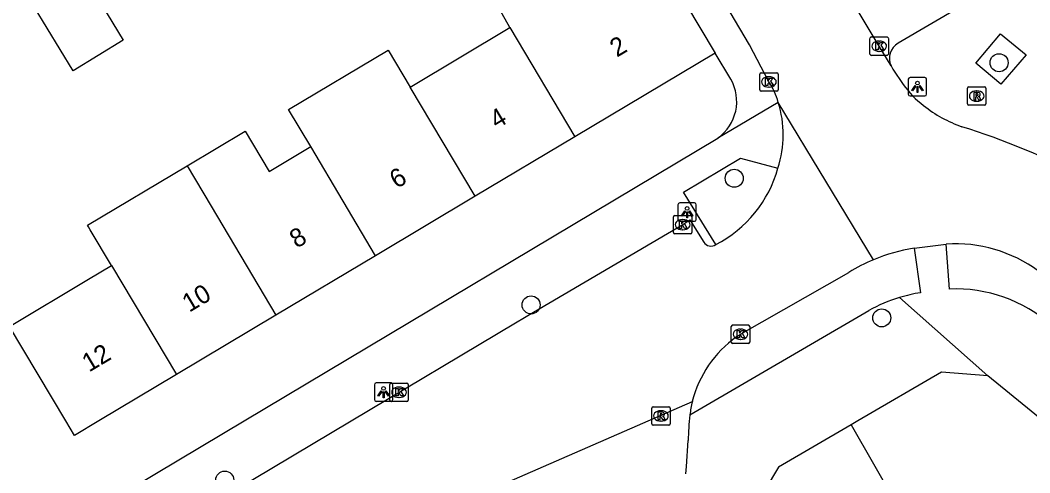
# Model space of a CAD drawing. Extents: x 159222 to 160346, y 381249 to 382166.
# Drawn here: x 160195.3 to 160250.2, y 381997.2 to 382021.7 of the extents above; entities that cross this region are included whole.
import ezdxf

# ---------------------------------------------------------------- set-up
doc = ezdxf.new("R2010")
doc.units = 0
for name, color, linetype in [('IMGEO_Boom', 7, 'Continuous'), ('IMGEO_Kolk', 7, 'Continuous'), ('IMGEO_Lichtpunt', 7, 'Continuous'), ('IMGEO_Pand', 7, 'Continuous'), ('IMGEO_Pand_nummerreeks', 7, 'Continuous'), ('IMGEO_Rijbaan_lokaal_open', 7, 'Continuous'), ('IMGEO_Rioolput', 7, 'Continuous'), ('IMGEO_Voetpad_open', 7, 'Continuous')]:
    doc.layers.add(name, color=color, linetype=linetype)

msp = doc.modelspace()

# ---------------------------------------------------------------- linework, layer by layer
at = {"layer": 'IMGEO_Boom'}
for centre in [(160248.507, 382019.429), (160234.114, 382013.158), (160223.079, 382006.288), (160242.131, 382005.588), (160206.437, 381996.785)]:
    msp.add_circle(centre, 0.489, dxfattribs=at)
at = {"layer": 'IMGEO_Kolk'}
for p, q in [((160241.566, 382020.825), (160242.418, 382020.825)), ((160241.491, 382019.899), (160241.491, 382020.751)), ((160241.979, 382020.605), (160242.004, 382020.605)), ((160242.492, 382020.751), (160242.492, 382019.899)), ((160242.418, 382019.825), (160241.566, 382019.825)), ((160242.002, 382020.045), (160241.977, 382020.045)), ((160235.499, 382017.96), (160235.499, 382018.812)), ((160235.574, 382018.886), (160236.426, 382018.886)), ((160235.987, 382018.666), (160236.012, 382018.666)), ((160236.5, 382018.812), (160236.5, 382017.96)), ((160236.01, 382018.106), (160235.985, 382018.106)), ((160236.426, 382017.886), (160235.574, 382017.886)), ((160230.815, 382010.217), (160230.815, 382011.069)), ((160230.89, 382011.143), (160231.742, 382011.143)), ((160231.303, 382010.923), (160231.328, 382010.923)), ((160231.816, 382011.069), (160231.816, 382010.217)), ((160231.742, 382010.143), (160230.89, 382010.143)), ((160231.326, 382010.363), (160231.301, 382010.363)), ((160233.956, 382004.274), (160233.956, 382005.126)), ((160234.031, 382005.2), (160234.883, 382005.2)), ((160234.444, 382004.98), (160234.469, 382004.98)), ((160234.957, 382005.126), (160234.957, 382004.274)), ((160234.467, 382004.42), (160234.442, 382004.42)), ((160234.883, 382004.2), (160234.031, 382004.2)), ((160215.407, 382001.125), (160215.407, 382001.977)), ((160215.482, 382002.051), (160216.334, 382002.051)), ((160215.895, 382001.831), (160215.92, 382001.831)), ((160216.408, 382001.977), (160216.408, 382001.125)), ((160216.334, 382001.051), (160215.482, 382001.051)), ((160215.918, 382001.271), (160215.893, 382001.271))]:
    msp.add_line(p, q, dxfattribs=at)
for points in [[(160241.566, 382020.825), (160242.418, 382020.825)], [(160241.491, 382019.899), (160241.491, 382020.751)], [(160241.812, 382020.525), (160241.935, 382020.525), (160241.935, 382020.374), (160242.065, 382020.525), (160242.229, 382020.525), (160242.083, 382020.374), (160242.236, 382020.125), (160242.084, 382020.125), (160241.999, 382020.289), (160241.935, 382020.222), (160241.935, 382020.125), (160241.812, 382020.125), (160241.812, 382020.525)], [(160242.492, 382020.751), (160242.492, 382019.899)], [(160242.418, 382019.825), (160241.566, 382019.825)], [(160235.499, 382017.96), (160235.499, 382018.812)], [(160235.574, 382018.886), (160236.426, 382018.886)], [(160236.5, 382018.812), (160236.5, 382017.96)], [(160235.82, 382018.586), (160235.943, 382018.586), (160235.943, 382018.435), (160236.073, 382018.586), (160236.237, 382018.586), (160236.091, 382018.435), (160236.244, 382018.186), (160236.092, 382018.186), (160236.007, 382018.35), (160235.943, 382018.283), (160235.943, 382018.186), (160235.82, 382018.186), (160235.82, 382018.586)], [(160236.426, 382017.886), (160235.574, 382017.886)], [(160230.815, 382010.217), (160230.815, 382011.069)], [(160230.89, 382011.143), (160231.742, 382011.143)], [(160231.816, 382011.069), (160231.816, 382010.217)], [(160231.136, 382010.843), (160231.259, 382010.843), (160231.259, 382010.692), (160231.389, 382010.843), (160231.553, 382010.843), (160231.407, 382010.692), (160231.56, 382010.443), (160231.408, 382010.443), (160231.323, 382010.607), (160231.259, 382010.54), (160231.259, 382010.443), (160231.136, 382010.443), (160231.136, 382010.843)], [(160231.742, 382010.143), (160230.89, 382010.143)], [(160233.956, 382004.274), (160233.956, 382005.126)], [(160234.031, 382005.2), (160234.883, 382005.2)], [(160234.277, 382004.9), (160234.4, 382004.9), (160234.4, 382004.749), (160234.53, 382004.9), (160234.694, 382004.9), (160234.548, 382004.749), (160234.701, 382004.5), (160234.549, 382004.5), (160234.464, 382004.664), (160234.4, 382004.597), (160234.4, 382004.5), (160234.277, 382004.5), (160234.277, 382004.9)], [(160234.957, 382005.126), (160234.957, 382004.274)], [(160234.883, 382004.2), (160234.031, 382004.2)], [(160215.407, 382001.125), (160215.407, 382001.977)], [(160215.482, 382002.051), (160216.334, 382002.051)], [(160215.728, 382001.751), (160215.851, 382001.751), (160215.851, 382001.6), (160215.981, 382001.751), (160216.145, 382001.751), (160215.999, 382001.6), (160216.152, 382001.351), (160216, 382001.351), (160215.915, 382001.515), (160215.851, 382001.448), (160215.851, 382001.351), (160215.728, 382001.351), (160215.728, 382001.751)], [(160216.408, 382001.977), (160216.408, 382001.125)], [(160216.334, 382001.051), (160215.482, 382001.051)]]:
    msp.add_lwpolyline(points, dxfattribs=at)
for centre, start, end in [((160241.568, 382020.749), 91.552, 178.448), ((160241.568, 382020.749), 91.552, 178.448), ((160242.416, 382020.749), 1.552, 88.448), ((160242.416, 382020.749), 1.552, 88.448), ((160241.568, 382019.901), 181.552, 268.448), ((160241.568, 382019.901), 181.552, 268.448), ((160242.416, 382019.901), 271.552, 358.448), ((160242.416, 382019.901), 271.552, 358.448), ((160235.576, 382018.81), 91.552, 178.448), ((160235.576, 382018.81), 91.552, 178.448), ((160236.424, 382018.81), 1.552, 88.448), ((160236.424, 382018.81), 1.552, 88.448), ((160235.576, 382017.962), 181.552, 268.448), ((160235.576, 382017.962), 181.552, 268.448), ((160236.424, 382017.962), 271.552, 358.448), ((160236.424, 382017.962), 271.552, 358.448), ((160230.892, 382011.067), 91.552, 178.448), ((160230.892, 382011.067), 91.552, 178.448), ((160231.74, 382011.067), 1.552, 88.448), ((160231.74, 382011.067), 1.552, 88.448), ((160230.892, 382010.219), 181.552, 268.448), ((160230.892, 382010.219), 181.552, 268.448), ((160231.74, 382010.219), 271.552, 358.448), ((160231.74, 382010.219), 271.552, 358.448), ((160234.033, 382005.124), 91.552, 178.448), ((160234.033, 382005.124), 91.552, 178.448), ((160234.881, 382005.124), 1.552, 88.448), ((160234.881, 382005.124), 1.552, 88.448), ((160234.033, 382004.276), 181.552, 268.448), ((160234.033, 382004.276), 181.552, 268.448), ((160234.881, 382004.276), 271.552, 358.448), ((160234.881, 382004.276), 271.552, 358.448), ((160215.484, 382001.975), 91.552, 178.448), ((160215.484, 382001.975), 91.552, 178.448), ((160216.332, 382001.975), 1.552, 88.448), ((160216.332, 382001.975), 1.552, 88.448), ((160215.484, 382001.127), 181.552, 268.448), ((160215.484, 382001.127), 181.552, 268.448), ((160216.332, 382001.127), 271.552, 358.448), ((160216.332, 382001.127), 271.552, 358.448)]:
    msp.add_arc(centre, 0.0765, start, end, dxfattribs=at)
for centre, major_axis, ratio, start_param, end_param in [((160241.978, 382020.325), (-0.387, 0.002), 0.722429, 4.712389, 7.853982), ((160242.003, 382020.325), (-0.39, 0.002), 0.717154, 1.570796, 4.712389), ((160235.986, 382018.386), (-0.387, 0.002), 0.722429, 4.712389, 7.853982), ((160236.011, 382018.386), (-0.39, 0.002), 0.717154, 1.570796, 4.712389), ((160231.302, 382010.643), (-0.387, 0.002), 0.722429, 4.712389, 7.853982), ((160231.327, 382010.643), (-0.39, 0.002), 0.717154, 1.570796, 4.712389), ((160234.443, 382004.7), (-0.387, 0.002), 0.722429, 4.712389, 7.853982), ((160234.468, 382004.7), (-0.39, 0.002), 0.717154, 1.570796, 4.712389), ((160215.894, 382001.551), (-0.387, 0.002), 0.722429, 4.712389, 7.853982), ((160215.919, 382001.551), (-0.39, 0.002), 0.717154, 1.570796, 4.712389)]:
    msp.add_ellipse(centre, major_axis=major_axis, ratio=ratio, start_param=start_param, end_param=end_param, dxfattribs=at)
at = {"layer": 'IMGEO_Lichtpunt'}
for p, q in [((160244.474, 382018.622), (160243.666, 382018.622)), ((160244.474, 382018.622), (160243.666, 382018.622)), ((160243.572, 382018.527), (160243.572, 382017.72)), ((160243.572, 382018.527), (160243.572, 382017.72)), ((160244.568, 382017.72), (160244.568, 382018.527)), ((160244.568, 382017.72), (160244.568, 382018.527)), ((160243.666, 382017.626), (160244.474, 382017.626)), ((160243.666, 382017.626), (160244.474, 382017.626)), ((160231.06, 382011.727), (160231.06, 382010.92)), ((160231.06, 382011.727), (160231.06, 382010.92)), ((160231.962, 382011.822), (160231.154, 382011.822)), ((160231.962, 382011.822), (160231.154, 382011.822)), ((160232.056, 382010.92), (160232.056, 382011.727)), ((160232.056, 382010.92), (160232.056, 382011.727)), ((160231.154, 382010.826), (160231.962, 382010.826)), ((160231.154, 382010.826), (160231.962, 382010.826)), ((160214.57, 382001.96), (160214.57, 382001.153)), ((160214.57, 382001.96), (160214.57, 382001.153)), ((160215.472, 382002.055), (160214.664, 382002.055)), ((160215.472, 382002.055), (160214.664, 382002.055)), ((160215.566, 382001.153), (160215.566, 382001.96)), ((160215.566, 382001.153), (160215.566, 382001.96)), ((160214.664, 382001.059), (160215.472, 382001.059)), ((160214.664, 382001.059), (160215.472, 382001.059))]:
    msp.add_line(p, q, dxfattribs=at)
for points in [[(160243.946, 382018.191), (160243.985, 382018.163), (160243.797, 382017.901), (160243.759, 382017.928), (160243.946, 382018.191)], [(160244.048, 382018.143), (160244.095, 382018.143), (160244.095, 382017.821), (160244.048, 382017.821), (160244.048, 382018.143)], [(160244.158, 382018.163), (160244.196, 382018.19), (160244.383, 382017.928), (160244.344, 382017.9), (160244.158, 382018.163)], [(160231.434, 382011.391), (160231.473, 382011.363), (160231.285, 382011.101), (160231.247, 382011.128), (160231.434, 382011.391)], [(160231.536, 382011.343), (160231.583, 382011.343), (160231.583, 382011.021), (160231.536, 382011.021), (160231.536, 382011.343)], [(160231.646, 382011.363), (160231.684, 382011.39), (160231.871, 382011.128), (160231.832, 382011.1), (160231.646, 382011.363)], [(160214.944, 382001.624), (160214.983, 382001.596), (160214.795, 382001.334), (160214.757, 382001.361), (160214.944, 382001.624)], [(160215.156, 382001.596), (160215.194, 382001.623), (160215.381, 382001.361), (160215.342, 382001.333), (160215.156, 382001.596)], [(160215.046, 382001.576), (160215.093, 382001.576), (160215.093, 382001.254), (160215.046, 382001.254), (160215.046, 382001.576)]]:
    msp.add_lwpolyline(points, dxfattribs=at)
for centre in [(160244.071, 382018.325), (160231.559, 382011.525), (160215.069, 382001.758)]:
    msp.add_circle(centre, 0.0994, dxfattribs=at)
for centre, start, end in [((160243.666, 382018.527), 90, 180), ((160243.666, 382018.527), 90, 180), ((160244.474, 382018.527), 0, 90), ((160244.474, 382018.527), 0, 90), ((160243.666, 382017.72), 180, 270), ((160243.666, 382017.72), 180, 270), ((160244.474, 382017.72), 270, 0), ((160244.474, 382017.72), 270, 360), ((160231.154, 382011.727), 90, 180), ((160231.154, 382011.727), 90, 180), ((160231.962, 382011.727), 0, 90), ((160231.962, 382011.727), 0, 90), ((160231.154, 382010.92), 180, 270), ((160231.154, 382010.92), 180, 270), ((160231.962, 382010.92), 270, 0), ((160231.962, 382010.92), 270, 360), ((160214.664, 382001.96), 90, 180), ((160214.664, 382001.96), 90, 180), ((160215.472, 382001.96), 0, 90), ((160215.472, 382001.96), 0, 90), ((160214.664, 382001.153), 180, 270), ((160214.664, 382001.153), 180, 270), ((160215.472, 382001.153), 270, 0), ((160215.472, 382001.153), 270, 360)]:
    msp.add_arc(centre, 0.0946, start, end, dxfattribs=at)
at = {"layer": 'IMGEO_Pand'}
for points in [[(160221.931, 382021.33), (160220.691, 382023.549), (160223.954, 382025.494), (160228.248, 382028.054)], [(160228.248, 382028.054), (160233.082, 382019.946)], [(160196.087, 382022.455), (160198.814, 382024.117), (160200.925, 382020.653), (160198.198, 382018.992), (160196.087, 382022.455)], [(160216.519, 382018.105), (160221.931, 382021.33)], [(160221.931, 382021.33), (160225.46, 382015.406)], [(160211.108, 382014.879), (160209.911, 382016.888), (160215.324, 382020.112), (160216.519, 382018.105)], [(160233.082, 382019.946), (160225.46, 382015.406)], [(160220.047, 382012.182), (160216.519, 382018.105)], [(160204.393, 382013.84), (160207.546, 382015.718), (160208.848, 382013.532), (160211.108, 382014.879)], [(160225.46, 382015.406), (160220.047, 382012.182)], [(160214.635, 382008.958), (160211.108, 382014.879)], [(160200.285, 382008.428), (160199.136, 382010.356), (160199.038, 382010.521), (160198.981, 382010.617), (160204.393, 382013.84)], [(160204.393, 382013.84), (160205.696, 382011.653), (160209.222, 382005.734)], [(160220.047, 382012.182), (160214.635, 382008.958)], [(160214.635, 382008.958), (160209.222, 382005.734)], [(160203.81, 382002.51), (160199.595, 382000), (160198.272, 381999.212), (160197.801, 382000), (160194.739, 382005.121), (160199.034, 382007.682), (160200.285, 382008.428)], [(160200.285, 382008.428), (160203.81, 382002.51)], [(160209.222, 382005.734), (160203.81, 382002.51)], [(160247.893, 382002.442), (160245.382, 382002.64), (160240.833, 382000), (160240.467, 381999.787)], [(160254.269, 381997.246), (160247.893, 382002.442)], [(160240.467, 381999.787), (160236.518, 381997.496), (160235.125, 381995.155), (160234.98, 381984.377)], [(160240.467, 381999.787), (160242.815, 381995.681), (160242.301, 381995.382), (160242.988, 381994.199), (160243.22, 381987.487), (160243.38, 381986.546), (160243.884, 381983.581)]]:
    msp.add_lwpolyline(points, dxfattribs=at)
at = {"layer": 'IMGEO_Rijbaan_lokaal_open'}
for points in [[(160242.637, 382019.252), (160241.991, 382020.325), (160236.902, 382028.808)], [(160236.001, 382018.386), (160234.942, 382020.406), (160231.787, 382025.73)], [(160242.637, 382019.252), (160242.736, 382019.087), (160243.295, 382018.254)], [(160241.682, 382008.739), (160236.506, 382017.278)], [(160198.41, 381991.126), (160213.308, 382000), (160222.241, 382005.321), (160223.218, 382005.903), (160231.316, 382010.643), (160231.712, 382010.896), (160232.464, 382009.692)], [(160243.884, 382009.373), (160245.635, 382009.589)], [(160234.236, 382004.55), (160234.457, 382004.7), (160240.337, 382008.053)], [(160221.766, 381996.654), (160231.841, 382001.047)], [(160231.489, 381997.12), (160231.518, 381997.53), (160231.615, 381998.931)]]:
    msp.add_lwpolyline(points, dxfattribs=at)
for centre, radius, start, end in [((160232.652, 382016.191), 4.005, 15.7574, 33.2473), ((160247.868, 382021.541), 5.632, 215.7083, 232.0669), ((160230.988, 382015.52), 5.792, 341.844, 17.6736), ((160248.98, 382022.946), 7.423, 231.9672, 250.3965), ((160234.308, 381977.006), 40.807, 62.6288, 72.632), ((160230.111, 382015.462), 6.615, 296.9924, 344.691), ((160232.847, 382009.933), 0.453, 212.2163, 305.9799), ((160245.548, 381999.451), 10.06, 99.5227, 112.6016), ((160246.144, 382002.037), 7.569, 53.5064, 93.8582), ((160245.561, 381999.472), 10.046, 112.7137, 121.3328), ((160237.761, 381999.57), 6.102, 125.291, 165.9882), ((160238.072, 381999.515), 6.416, 166.1868, 172.802), ((160246.378, 381998.66), 14.766, 173.5492, 178.9487)]:
    msp.add_arc(centre, radius, start, end, dxfattribs=at)
at = {"layer": 'IMGEO_Rioolput'}
for p, q in [((160246.864, 382018.12), (160247.716, 382018.12)), ((160246.789, 382017.194), (160246.789, 382018.046)), ((160247.277, 382017.9), (160247.302, 382017.9)), ((160247.79, 382018.046), (160247.79, 382017.194)), ((160247.716, 382017.12), (160246.864, 382017.12)), ((160247.3, 382017.34), (160247.275, 382017.34)), ((160229.634, 381999.841), (160229.634, 382000.693)), ((160229.709, 382000.767), (160230.561, 382000.767)), ((160230.122, 382000.547), (160230.147, 382000.547)), ((160230.635, 382000.693), (160230.635, 381999.841)), ((160230.145, 381999.987), (160230.12, 381999.987)), ((160230.561, 381999.767), (160229.709, 381999.767))]:
    msp.add_line(p, q, dxfattribs=at)
for points in [[(160246.864, 382018.12), (160247.716, 382018.12)], [(160246.789, 382017.194), (160246.789, 382018.046)], [(160247.378, 382017.818), (160247.126, 382017.82), (160247.126, 382017.42)], [(160247.126, 382017.42), (160247.25, 382017.42), (160247.25, 382017.582), (160247.261, 382017.582)], [(160247.304, 382017.739), (160247.25, 382017.739), (160247.25, 382017.658)], [(160247.25, 382017.658), (160247.302, 382017.658)], [(160247.308, 382017.553), (160247.379, 382017.42), (160247.519, 382017.42), (160247.454, 382017.546)], [(160247.79, 382018.046), (160247.79, 382017.194)], [(160247.716, 382017.12), (160246.864, 382017.12)], [(160229.634, 381999.841), (160229.634, 382000.693)], [(160229.709, 382000.767), (160230.561, 382000.767)], [(160230.635, 382000.693), (160230.635, 381999.841)], [(160230.223, 382000.465), (160229.971, 382000.467), (160229.971, 382000.067)], [(160229.971, 382000.067), (160230.095, 382000.067), (160230.095, 382000.229), (160230.106, 382000.229)], [(160230.149, 382000.386), (160230.095, 382000.386), (160230.095, 382000.305)], [(160230.095, 382000.305), (160230.147, 382000.305)], [(160230.153, 382000.2), (160230.224, 382000.067), (160230.364, 382000.067), (160230.299, 382000.193)], [(160230.561, 381999.767), (160229.709, 381999.767)]]:
    msp.add_lwpolyline(points, dxfattribs=at)
for centre, radius, start, end in [((160246.866, 382018.044), 0.0765, 91.552, 178.448), ((160246.866, 382018.044), 0.0765, 91.552, 178.448), ((160247.714, 382018.044), 0.0765, 1.552, 88.448), ((160247.714, 382018.044), 0.0765, 1.552, 88.448), ((160247.26, 382017.529), 0.0533, 26.0293, 88.6989), ((160247.286, 382017.847), 0.19, 274.7715, 282.9687), ((160247.31, 382017.643), 0.0964, 77.0061, 93.1865), ((160247.324, 382017.7), 0.0378, 276.6634, 79.6772), ((160247.377, 382017.708), 0.109, 350.3612, 89.416), ((160247.375, 382017.708), 0.112, 277.5842, 350.9817), ((160247.359, 382017.493), 0.108, 29.5134, 73.7905), ((160246.866, 382017.196), 0.0765, 181.552, 268.448), ((160246.866, 382017.196), 0.0765, 181.552, 268.448), ((160247.714, 382017.196), 0.0765, 271.552, 358.448), ((160247.714, 382017.196), 0.0765, 271.552, 358.448), ((160229.711, 382000.691), 0.0765, 91.552, 178.448), ((160229.711, 382000.691), 0.0765, 91.552, 178.448), ((160230.559, 382000.691), 0.0765, 1.552, 88.448), ((160230.559, 382000.691), 0.0765, 1.552, 88.448), ((160230.105, 382000.176), 0.0533, 26.0293, 88.6989), ((160230.131, 382000.494), 0.19, 274.7715, 282.9687), ((160230.155, 382000.29), 0.0964, 77.0061, 93.1865), ((160230.169, 382000.347), 0.0378, 276.6634, 79.6772), ((160230.222, 382000.355), 0.109, 350.3612, 89.416), ((160230.22, 382000.355), 0.112, 277.5842, 350.9817), ((160230.204, 382000.14), 0.108, 29.5134, 73.7905), ((160229.711, 381999.843), 0.0765, 181.552, 268.448), ((160229.711, 381999.843), 0.0765, 181.552, 268.448), ((160230.559, 381999.843), 0.0765, 271.552, 358.448), ((160230.559, 381999.843), 0.0765, 271.552, 358.448)]:
    msp.add_arc(centre, radius, start, end, dxfattribs=at)
for centre, major_axis, ratio, start_param, end_param in [((160247.276, 382017.62), (-0.387, 0.002), 0.722429, 4.712389, 7.853982), ((160247.301, 382017.62), (-0.39, 0.002), 0.717154, 1.570796, 4.712389), ((160230.121, 382000.267), (-0.387, 0.002), 0.722429, 4.712389, 7.853982), ((160230.146, 382000.267), (-0.39, 0.002), 0.717154, 1.570796, 4.712389)]:
    msp.add_ellipse(centre, major_axis=major_axis, ratio=ratio, start_param=start_param, end_param=end_param, dxfattribs=at)
at = {"layer": 'IMGEO_Voetpad_open'}
for points in [[(160246.46, 382022.496), (160243.029, 382020.483)], [(160249.972, 382019.861), (160248.607, 382018.269), (160247.245, 382019.401), (160248.59, 382020.992), (160249.972, 382019.861)], [(160233.929, 382018.543), (160233.082, 382019.946)], [(160236.506, 382017.278), (160233.231, 382015.343)], [(160200.308, 381995.717), (160207.493, 382000), (160233.231, 382015.343)], [(160233.113, 382009.567), (160231.366, 382012.403), (160234.454, 382014.259), (160236.491, 382013.715)], [(160243.884, 382009.373), (160244.238, 382006.95)], [(160245.808, 382007.146), (160245.635, 382009.589)], [(160243.099, 382006.692), (160247.893, 382002.442)], [(160231.706, 382000.319), (160241.426, 382005.978)]]:
    msp.add_lwpolyline(points, dxfattribs=at)
for centre, radius, start, end in [((160243.494, 382019.657), 0.948, 119.3889, 205.284), ((160231.806, 382017.33), 2.445, 305.646, 29.7442), ((160246.187, 381999.465), 7.69, 47.976, 92.8254), ((160245.53, 381998.68), 8.373, 106.8756, 119.3479), ((160245.503, 381998.72), 8.327, 98.7416, 106.7843)]:
    msp.add_arc(centre, radius, start, end, dxfattribs=at)

# ---------------------------------------------------------------- texts
at = {"layer": 'IMGEO_Pand_nummerreeks'}
for s, rotation, p in [('2', 30.7794, (160227.743, 382019.7)), ('4', 30.7794, (160221.215, 382015.811)), ('6', 30.7793, (160215.777, 382012.572)), ('8', 30.7794, (160210.344, 382009.336)), ('10', 30.7793, (160204.51, 382005.861)), ('12', 30.7794, (160199.068, 382002.619))]:
    msp.add_text(s, height=1, rotation=rotation, dxfattribs=at).set_placement(p)

doc.saveas('drawing.dxf')
